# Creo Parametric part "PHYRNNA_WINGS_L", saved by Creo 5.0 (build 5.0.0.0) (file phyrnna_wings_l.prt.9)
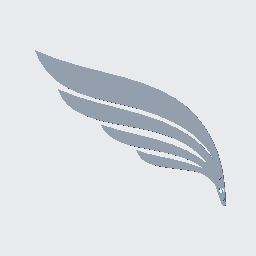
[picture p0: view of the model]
Units: Inch lbm Second (Pro/E Default); INCH, POUND, SECS

Created from: INLBS_PART_SOLID.PRT

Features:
  1. datum plane "RIGHT"
  2. datum plane "TOP"
  3. datum plane "FRONT"
  4. coordinate system
  5. sketch "Sketch 1"
  6. sketch "Sketch 2"
  7. extrusion "Extrude 1"
  8. sketch "Sketch 3"
  9. extrusion "Extrude 2"

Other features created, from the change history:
  extrusion "Extrude 1"
  sketch "Sketch 2"
  extrusion "Extrude 2"

Other named items: WING_S, REFERENCE, WING_E, PEG_S, PEG_E

Surfaces: 8 tabulated cylinder, 3 plane, 3 cylinder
